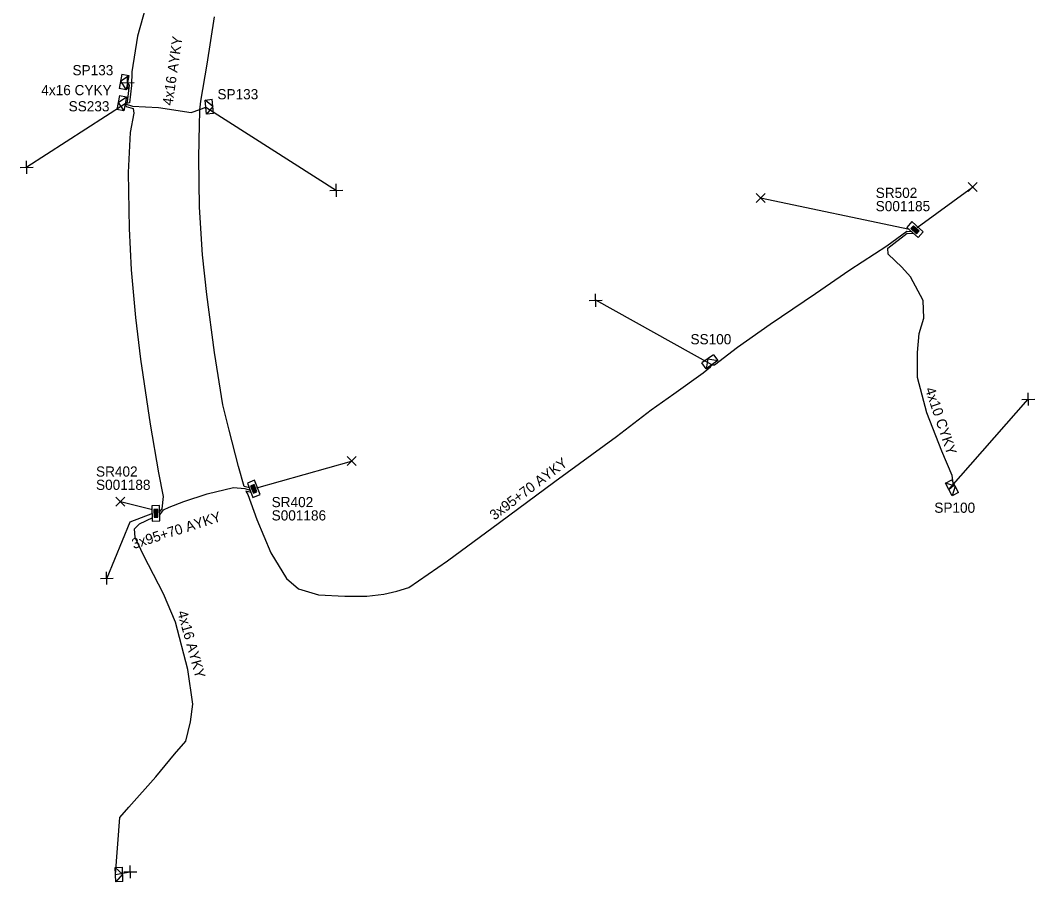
# Model space of a CAD drawing. Extents: x -762504 to -761250, y -1152974 to -1152253.
# Drawn here: x -761785.5 to -761686.3, y -1152447.7 to -1152363.5 of the extents above; entities that cross this region are included whole.
import ezdxf

# ---------------------------------------------------------------- set-up
doc = ezdxf.new("R2010")
doc.units = 0
for name, color, linetype in [('Vrstva 28', 7, 'Continuous'), ('Vrstva 29', 7, 'Continuous'), ('Vrstva 30', 7, 'Continuous'), ('Vrstva 31', 7, 'Continuous'), ('Vrstva 33', 7, 'Continuous'), ('Vrstva 34', 7, 'Continuous'), ('Vrstva 5', 7, 'Continuous'), ('Vrstva 52', 7, 'Continuous'), ('Vrstva 54', 7, 'Continuous'), ('Vrstva 59', 7, 'Continuous'), ('Vrstva 6', 7, 'Continuous')]:
    doc.layers.add(name, color=color, linetype=linetype)

msp = doc.modelspace()

# ---------------------------------------------------------------- linework, layer by layer
at = {"layer": 'Vrstva 28'}
for points in [[(-761698.339, -1152383.192), (-761698.841, -1152383.749)], [(-761697.225, -1152384.196), (-761698.339, -1152383.192)], [(-761698.841, -1152383.749), (-761697.727, -1152384.753)], [(-761698.181, -1152383.589), (-761698.434, -1152383.87)], [(-761698.434, -1152383.87), (-761697.881, -1152384.368)], [(-761698.177, -1152383.656), (-761698.367, -1152383.867)], [(-761698.367, -1152383.867), (-761697.884, -1152384.301)], [(-761698.174, -1152383.723), (-761698.3, -1152383.863)], [(-761698.3, -1152383.863), (-761697.888, -1152384.235)], [(-761698.17, -1152383.789), (-761698.233, -1152383.86)], [(-761698.233, -1152383.86), (-761697.891, -1152384.168)], [(-761697.628, -1152384.087), (-761698.181, -1152383.589)], [(-761697.694, -1152384.091), (-761698.177, -1152383.656)], [(-761697.761, -1152384.094), (-761698.174, -1152383.723)], [(-761697.89, -1152384.105), (-761698.171, -1152383.852)], [(-761697.828, -1152384.098), (-761698.17, -1152383.789)], [(-761697.891, -1152384.168), (-761697.828, -1152384.098)], [(-761697.888, -1152384.235), (-761697.761, -1152384.094)], [(-761697.884, -1152384.301), (-761697.694, -1152384.091)], [(-761697.881, -1152384.368), (-761697.628, -1152384.087)], [(-761697.727, -1152384.753), (-761697.225, -1152384.196)], [(-761762.593, -1152408.47), (-761763.293, -1152408.739)], [(-761763.293, -1152408.739), (-761762.755, -1152410.14)], [(-761762.632, -1152408.896), (-761762.984, -1152409.032)], [(-761762.984, -1152409.032), (-761762.718, -1152409.727)], [(-761762.659, -1152408.957), (-761762.923, -1152409.059)], [(-761762.923, -1152409.059), (-761762.69, -1152409.666)], [(-761762.686, -1152409.018), (-761762.862, -1152409.086)], [(-761762.862, -1152409.086), (-761762.663, -1152409.604)], [(-761762.713, -1152409.079), (-761762.801, -1152409.113)], [(-761762.801, -1152409.113), (-761762.636, -1152409.543)], [(-761762.548, -1152409.51), (-761762.713, -1152409.079)], [(-761762.487, -1152409.537), (-761762.686, -1152409.018)], [(-761762.426, -1152409.564), (-761762.659, -1152408.957)], [(-761762.365, -1152409.591), (-761762.632, -1152408.896)], [(-761762.055, -1152409.871), (-761762.593, -1152408.47)], [(-761762.755, -1152410.14), (-761762.055, -1152409.871)], [(-761762.607, -1152409.488), (-761762.742, -1152409.135)], [(-761762.718, -1152409.727), (-761762.365, -1152409.591)], [(-761762.69, -1152409.666), (-761762.426, -1152409.564)], [(-761762.663, -1152409.604), (-761762.487, -1152409.537)], [(-761762.636, -1152409.543), (-761762.548, -1152409.51)], [(-761771.903, -1152410.952), (-761772.652, -1152410.979)], [(-761772.652, -1152410.979), (-761772.6, -1152412.478)], [(-761771.85, -1152412.451), (-761771.903, -1152410.952)], [(-761772.073, -1152411.331), (-761772.45, -1152411.344)], [(-761772.45, -1152411.344), (-761772.424, -1152412.087)], [(-761772.424, -1152412.087), (-761772.047, -1152412.074)], [(-761772.118, -1152411.379), (-761772.401, -1152411.389)], [(-761772.401, -1152411.389), (-761772.379, -1152412.039)], [(-761772.379, -1152412.039), (-761772.096, -1152412.029)], [(-761772.164, -1152411.428), (-761772.353, -1152411.435)], [(-761772.353, -1152411.435), (-761772.333, -1152411.99)], [(-761772.333, -1152411.99), (-761772.144, -1152411.983)], [(-761772.209, -1152411.477), (-761772.304, -1152411.48)], [(-761772.304, -1152411.48), (-761772.288, -1152411.941)], [(-761772.288, -1152411.941), (-761772.193, -1152411.938)], [(-761772.255, -1152411.52), (-761772.242, -1152411.898)], [(-761772.193, -1152411.938), (-761772.209, -1152411.477)], [(-761772.144, -1152411.983), (-761772.164, -1152411.428)], [(-761772.096, -1152412.029), (-761772.118, -1152411.379)], [(-761772.047, -1152412.074), (-761772.073, -1152411.331)], [(-761772.6, -1152412.478), (-761771.85, -1152412.451)]]:
    msp.add_lwpolyline(points, dxfattribs=at)
at = {"layer": 'Vrstva 31'}
for points in [[(-761775.564, -1152368.787), (-761775.831, -1152370.161)], [(-761775.564, -1152368.787), (-761774.877, -1152368.92), (-761775.144, -1152370.294), (-761775.831, -1152370.161)], [(-761775.697, -1152369.474), (-761774.877, -1152368.92)], [(-761775.697, -1152369.474), (-761775.144, -1152370.294)], [(-761775.793, -1152370.856), (-761776.061, -1152372.231)], [(-761775.793, -1152370.856), (-761775.106, -1152370.99), (-761775.373, -1152372.364), (-761776.061, -1152372.231)], [(-761775.927, -1152371.544), (-761775.106, -1152370.99)], [(-761766.6, -1152372.626), (-761767.296, -1152372.699), (-761767.442, -1152371.307), (-761766.746, -1152371.233)], [(-761766.673, -1152371.93), (-761767.442, -1152371.307)], [(-761766.6, -1152372.626), (-761766.746, -1152371.233)], [(-761775.927, -1152371.544), (-761775.373, -1152372.364)], [(-761766.673, -1152371.93), (-761767.296, -1152372.699)], [(-761717.716, -1152396.203), (-761718.863, -1152397.006)], [(-761717.716, -1152396.203), (-761717.314, -1152396.777), (-761718.461, -1152397.58), (-761718.863, -1152397.006)], [(-761718.289, -1152396.605), (-761718.461, -1152397.58)], [(-761718.289, -1152396.605), (-761717.314, -1152396.777)], [(-761693.782, -1152409.662), (-761694.4, -1152409.99), (-761695.057, -1152408.754), (-761694.439, -1152408.426)], [(-761694.11, -1152409.044), (-761695.057, -1152408.754)], [(-761693.782, -1152409.662), (-761694.439, -1152408.426)], [(-761694.11, -1152409.044), (-761694.4, -1152409.99)], [(-761775.476, -1152447.688), (-761776.175, -1152447.712), (-761776.224, -1152446.313), (-761775.524, -1152446.289)], [(-761775.5, -1152446.988), (-761776.224, -1152446.313)], [(-761775.476, -1152447.688), (-761775.524, -1152446.289)], [(-761775.5, -1152446.988), (-761776.175, -1152447.712)]]:
    msp.add_lwpolyline(points, dxfattribs=at)
at = {"layer": 'Vrstva 34'}
for points in [[(-761774.999, -1152370.235), (-761775.021, -1152368.985)], [(-761775.635, -1152369.621), (-761774.385, -1152369.599)], [(-761784.869, -1152378.505), (-761784.891, -1152377.255)], [(-761785.505, -1152377.891), (-761784.255, -1152377.869)], [(-761755.225, -1152380.141), (-761753.975, -1152380.119)], [(-761754.589, -1152380.755), (-761754.611, -1152379.505)], [(-761692.842, -1152379.368), (-761691.958, -1152380.252)], [(-761692.842, -1152380.252), (-761691.958, -1152379.368)], [(-761713.572, -1152380.438), (-761712.688, -1152381.322)], [(-761713.572, -1152381.322), (-761712.688, -1152380.438)], [(-761729.239, -1152391.505), (-761729.261, -1152390.255)], [(-761729.875, -1152390.891), (-761728.625, -1152390.869)], [(-761686.939, -1152401.175), (-761686.961, -1152399.925)], [(-761687.575, -1152400.561), (-761686.325, -1152400.539)], [(-761753.562, -1152406.158), (-761752.678, -1152407.042)], [(-761753.562, -1152407.042), (-761752.678, -1152406.158)], [(-761776.152, -1152410.128), (-761775.268, -1152411.012)], [(-761776.152, -1152411.012), (-761775.268, -1152410.128)], [(-761777.675, -1152418.061), (-761776.425, -1152418.039)], [(-761777.039, -1152418.675), (-761777.061, -1152417.425)], [(-761775.375, -1152446.761), (-761774.125, -1152446.739)], [(-761774.739, -1152447.375), (-761774.761, -1152446.125)]]:
    msp.add_lwpolyline(points, dxfattribs=at)
at = {"layer": 'Vrstva 5'}
for points in [[(-761773.23, -1152362.16), (-761774.04, -1152365.05), (-761774.6, -1152368.56), (-761774.64, -1152369.88), (-761774.84, -1152371.59), (-761775.24, -1152371.68), (-761775.15, -1152371.92), (-761774.48, -1152372.12), (-761774.4, -1152372.59), (-761774.75, -1152374.48), (-761774.95, -1152378.37), (-761774.85, -1152383.85), (-761774.68, -1152387.91), (-761774.24, -1152392.57), (-761773.75, -1152396.62), (-761772.82, -1152403), (-761771.99, -1152407.76), (-761771.52, -1152410.05), (-761771.67, -1152411.25), (-761771.89, -1152411.54)], [(-761763.11, -1152409.21), (-761763.62, -1152409.07), (-761764.16, -1152407.12), (-761765.09, -1152403.58), (-761765.7, -1152401.09), (-761766.51, -1152395.99), (-761767.28, -1152390.32), (-761767.68, -1152386.44), (-761767.97, -1152381.79), (-761768.06, -1152376.91), (-761767.99, -1152373.7), (-761767.96, -1152372.45), (-761767.95, -1152372.23), (-761767.92, -1152372), (-761767.84, -1152371.4), (-761767.25, -1152367.79), (-761766.52, -1152363.16)], [(-761762.94, -1152409.67), (-761763.44, -1152409.53), (-761763.27, -1152409.87), (-761762.39, -1152412.29), (-761761, -1152415.58), (-761759.49, -1152418.08), (-761758.29, -1152419.08), (-761756.36, -1152419.68), (-761753.78, -1152419.8), (-761751.62, -1152419.79), (-761749.97, -1152419.62), (-761748.7, -1152419.32), (-761747.53, -1152418.96), (-761743.73, -1152416.36), (-761738.65, -1152412.61), (-761733.23, -1152408.6), (-761727.21, -1152404.18), (-761723.84, -1152401.58), (-761721.62, -1152400.02), (-761718.74, -1152397.97), (-761718.01, -1152397.38), (-761717.89, -1152397.18), (-761717.62, -1152397.18), (-761715.38, -1152395.45), (-761712.18, -1152393.21), (-761707.77, -1152390.21), (-761704.41, -1152387.89), (-761700.77, -1152385.57), (-761698.84, -1152384.12), (-761698.4, -1152384.14)], [(-761694.73, -1152409.37), (-761694.26, -1152408.98), (-761694.39, -1152408.02), (-761695.41, -1152405.64), (-761696.86, -1152401.88), (-761697.78, -1152398.42), (-761697.79, -1152395.99), (-761697.63, -1152394.13), (-761697.15, -1152392.64), (-761697.23, -1152390.91), (-761698.46, -1152388.58), (-761699.32, -1152387.65), (-761700.64, -1152386.38), (-761700.7, -1152385.77), (-761698.78, -1152384.32), (-761698.16, -1152384.36)], [(-761771.87, -1152411.86), (-761771.49, -1152411.35), (-761770.95, -1152411.09), (-761769.53, -1152410.54), (-761767.23, -1152409.79), (-761764.66, -1152409.17), (-761763.56, -1152409.29), (-761763.02, -1152409.44)], [(-761776.2, -1152447.01), (-761775.76, -1152441.45), (-761774.88, -1152440.44), (-761772.24, -1152437.45), (-761770.44, -1152435.25), (-761769.33, -1152433.99), (-761768.86, -1152432.08), (-761768.62, -1152430.35), (-761769.11, -1152426.96), (-761770.33, -1152422.35), (-761771.5, -1152419.56), (-761772.47, -1152417.67), (-761773.46, -1152415.78), (-761774.27, -1152414.06), (-761774.34, -1152413.21), (-761773.86, -1152412.72), (-761772.55, -1152412.1)]]:
    msp.add_lwpolyline(points, dxfattribs=at)
at = {"layer": 'Vrstva 52'}
for points in [[(-761775.24, -1152371.68), (-761775.03, -1152371.48), (-761774.84, -1152369.86), (-761775.01, -1152369.61)], [(-761775.24, -1152371.68), (-761774.52, -1152371.9), (-761772, -1152372.04), (-761768.81, -1152372.51), (-761767.95, -1152372.23), (-761767.37, -1152372)]]:
    msp.add_lwpolyline(points, dxfattribs=at)
at = {"layer": 'Vrstva 59'}
for points in [[(-761775.24, -1152371.68), (-761784.88, -1152377.88)], [(-761767.37, -1152372), (-761754.6, -1152380.13)], [(-761697.83, -1152383.76), (-761692.4, -1152379.81)], [(-761698.57, -1152383.95), (-761713.13, -1152380.88)], [(-761717.89, -1152397.18), (-761729.25, -1152390.88)], [(-761694.73, -1152409.37), (-761686.95, -1152400.55)], [(-761762.37, -1152409.2), (-761753.12, -1152406.6)], [(-761772.59, -1152411.36), (-761775.71, -1152410.57)], [(-761772.57, -1152411.73), (-761774.79, -1152412.57), (-761777.05, -1152418.05)], [(-761776.2, -1152447.01), (-761774.75, -1152446.75)]]:
    msp.add_lwpolyline(points, dxfattribs=at)

# ---------------------------------------------------------------- texts
at = {"layer": 'Vrstva 29'}
for s, p in [('S001185', (-761701.87, -1152382.17)), ('S001188', (-761778.1, -1152409.41)), ('S001186', (-761760.93, -1152412.4))]:
    msp.add_text(s, height=0.9943, dxfattribs=at).set_placement(p)
at = {"layer": 'Vrstva 30'}
for s, p in [('SR502', (-761701.87, -1152380.87)), ('SR402', (-761778.1, -1152408.11)), ('SR402', (-761760.93, -1152411.1))]:
    msp.add_text(s, height=0.9943, dxfattribs=at).set_placement(p)
at = {"layer": 'Vrstva 33'}
for s, p in [('SP133', (-761780.4, -1152368.88)), ('SP133', (-761766.23, -1152371.23)), ('SS233', (-761780.78, -1152372.41)), ('SS100', (-761719.98, -1152395.18)), ('SP100', (-761696.14, -1152411.65))]:
    msp.add_text(s, height=0.9943, dxfattribs=at).set_placement(p)
at = {"layer": 'Vrstva 54'}
msp.add_text('4x16 AYKY', height=0.9943, rotation=81.6186, dxfattribs=at).set_placement((-761770.63, -1152371.88))
msp.add_text('4x16 CYKY', height=0.9943, dxfattribs=at).set_placement((-761783.45, -1152370.83))
at = {"layer": 'Vrstva 6'}
for s, height, rotation, p in [('4x10 CYKY', 0.9943, 288.58897, (-761697.06, -1152399.56)), ('3x95+70 AYKY', 0.99429, 36.98058, (-761739.15, -1152412.42)), ('3x95+70 AYKY', 0.99429, 17.68439, (-761774.42, -1152415.2)), ('4x16 AYKY', 0.9943, 285.52411, (-761770.16, -1152421.36))]:
    msp.add_text(s, height=height, rotation=rotation, dxfattribs=at).set_placement(p)

doc.saveas('drawing.dxf')
